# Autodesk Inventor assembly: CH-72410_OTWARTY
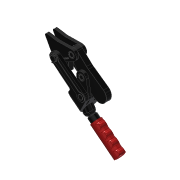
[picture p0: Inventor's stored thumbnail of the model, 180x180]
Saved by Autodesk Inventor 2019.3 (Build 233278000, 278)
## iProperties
Company: Î¢ÈíÖÐ¹ú
Created: 2012-10
Part Number: CH-72410_OTWARTY
Material: Ogólny
Description: STEP AP203
Document SubType Name: Assembly
Designer: CADENGINEERING4
Stock Number: DOCISKI CIĘŻIE
Sending System: SolidWorks 2010
Preprocessor: SwSTEP 2.0
Title: CH-72410.STEP
Author: Î¢ÈíÓÃ»§
Revision Number: ÈÎºÎ
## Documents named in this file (13)
- D:\Vault_2016\Projekty\NASZ KATALOG\CLAMPTEK\STRONA\Heavy duty weldables\CH-72410\CH-72410_OTWARTY.iam
- D:\Vault_2016\Projekty\NASZ KATALOG\CLAMPTEK\STRONA\Heavy duty weldables\CH-72410\72425-10.ipt
- D:\Vault_2016\Projekty\NASZ KATALOG\CLAMPTEK\STRONA\Heavy duty weldables\CH-72410\72425-06.ipt
- D:\Vault_2016\Projekty\NASZ KATALOG\CLAMPTEK\STRONA\Heavy duty weldables\CH-72410\M12.ipt
- D:\Vault_2016\Projekty\NASZ KATALOG\CLAMPTEK\STRONA\Heavy duty weldables\CH-72410\72425-07.ipt
- D:\Vault_2016\Projekty\NASZ KATALOG\CLAMPTEK\STRONA\Heavy duty weldables\CH-72410\CH-72410-03.ipt
- D:\Vault_2016\Projekty\NASZ KATALOG\CLAMPTEK\STRONA\Heavy duty weldables\CH-72410\72425-08.ipt
- D:\Vault_2016\Projekty\NASZ KATALOG\CLAMPTEK\STRONA\Heavy duty weldables\CH-72410\72425-11.ipt
- D:\Vault_2016\Projekty\NASZ KATALOG\CLAMPTEK\STRONA\Heavy duty weldables\CH-72410\CH-72410-01.ipt
- D:\Vault_2016\Projekty\NASZ KATALOG\CLAMPTEK\STRONA\Heavy duty weldables\CH-72410\CH-72410-02-02.ipt
- D:\Vault_2016\Projekty\NASZ KATALOG\CLAMPTEK\STRONA\Heavy duty weldables\CH-72410\CH-72410-02.ipt
- D:\Vault_2016\Projekty\NASZ KATALOG\CLAMPTEK\STRONA\Heavy duty weldables\CH-72410\72425-04.ipt
- D:\Vault_2016\Projekty\NASZ KATALOG\CLAMPTEK\STRONA\Heavy duty weldables\CH-72410\72425-03.ipt
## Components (23 placed, 12 different names)
1. CH-72410-01_12
2. CH-72410-02-02_14
3. CH-72410-02_17
4. 72425-10:2 — Zestawiające:2, Zestawiające:3, Zestawiające:4, Zestawiające:5, Zestawiające:20, Zestawiające:21, Zestawiające:42, Zestawiające:46
5. 72425-06:11 — Zestawiające:5, Zestawiające:19
6. M12:2 — Zestawiające:3, Zestawiające:22, Zestawiające:43
7. 72425-06:12 — Zestawiające:21, Równoległe:2
8. 72425-06:13 — Zestawiające:42, Zestawiające:43
9. 72425-07:2 — Zestawiające:9, Równoległe:1, Zestawiające:14, Zestawiające:17, Równoległe:3, Zestawiające:27, Zestawiające:33, Zestawiające:35, Zestawiające:36, Równoległe:8
10. 72425-06:14 — Zestawiające:6, Zestawiające:29, Zestawiające:31
11. CH-72410-03:2 — Zestawiające:7, Zestawiające:10, Zestawiające:11, Zestawiające:16, Zestawiające:25, Zestawiające:26, Zestawiające:28, Równoległe:4, Zestawiające:31, Zestawiające:32, Zestawiające:41
12. 72425-06:15 — Zestawiające:15, Zestawiające:39, Zestawiające:40, Równoległe:7
13. 72425-08:3 — Zestawiające:15, Zestawiające:16, Zestawiające:37, Zestawiające:38, Zestawiające:39, Zestawiające:41, Równoległe:6
14. 72425-11:2 — Zestawiające:1, Zestawiające:44
15. 72425-08:4 — Zestawiające:6, Zestawiające:7, Zestawiające:8, Zestawiające:28, Zestawiające:29, Zestawiające:30, Równoległe:4
16. 72425-06:16 — Zestawiające:37, Równoległe:5
17. 72425-06:17 — Zestawiające:2, Zestawiające:18
18. 72425-06:18 — Zestawiające:14, Zestawiające:35, Równoległe:9
19. 72425-06:19 — Zestawiające:8, Zestawiające:30, Zestawiające:32
20. 72425-06:20 — Zestawiające:33, Zestawiające:34, Równoległe:10
21. 72425-04:2 — Zestawiające:1, Zestawiające:4, Zestawiające:9, Równoległe:1, Zestawiające:12, Zestawiające:13, Zestawiające:18, Zestawiające:19, Zestawiające:20, Równoległe:2, Zestawiające:22, Zestawiające:23, Zestawiające:24, Równoległe:3, Zestawiające:27, Zestawiające:44, Zestawiające:46
22. 72425-03:3 — Zestawiające:11, Zestawiające:13, Zestawiające:24, Zestawiające:25, Zestawiające:34, Zestawiające:38, Równoległe:5, Równoległe:6, Równoległe:10
23. 72425-03:4 — Zestawiające:10, Zestawiające:12, Zestawiające:17, Zestawiające:23, Zestawiające:26, Zestawiające:36, Zestawiające:40, Równoległe:7, Równoległe:8, Równoległe:9
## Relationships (55: Mate 45, Flush 10)
- Zestawiające:1 [Mate]: 72425-11:2 ↔ 72425-04:2
- Zestawiające:2 [Mate]: 72425-10:2 ↔ 72425-06:17
- Zestawiające:3 [Mate]: 72425-10:2 ↔ M12:2
- Zestawiające:4 [Mate]: 72425-10:2 ↔ 72425-04:2
- Zestawiające:5 [Mate]: 72425-10:2 ↔ 72425-06:11
- Zestawiające:6 [Mate]: 72425-06:14 ↔ 72425-08:4
- Zestawiające:7 [Mate]: CH-72410-03:2 ↔ 72425-08:4
- Zestawiające:8 [Mate]: 72425-08:4 ↔ 72425-06:19
- Zestawiające:9 [Mate]: 72425-07:2 ↔ 72425-04:2
- Równoległe:1 [Flush]: 72425-07:2 ↔ 72425-04:2
- Zestawiające:10 [Mate]: CH-72410-03:2 ↔ 72425-03:4
- Zestawiające:11 [Mate]: CH-72410-03:2 ↔ 72425-03:3
- Zestawiające:12 [Mate]: 72425-04:2 ↔ 72425-03:4
- Zestawiające:13 [Mate]: 72425-04:2 ↔ 72425-03:3
- Zestawiające:14 [Mate]: 72425-07:2 ↔ 72425-06:18
- Zestawiające:15 [Mate]: 72425-06:15 ↔ 72425-08:3
- Zestawiające:16 [Mate]: CH-72410-03:2 ↔ 72425-08:3
- Zestawiające:17 [Mate]: 72425-07:2 ↔ 72425-03:4
- Zestawiające:18 [Mate]: 72425-06:17 ↔ 72425-04:2
- Zestawiające:19 [Mate]: 72425-06:11 ↔ 72425-04:2
- Zestawiające:20 [Mate]: 72425-10:2 ↔ 72425-04:2
- Zestawiające:21 [Mate]: 72425-10:2 ↔ 72425-06:12
- Równoległe:2 [Flush]: 72425-06:12 ↔ 72425-04:2
- Zestawiające:22 [Mate]: M12:2 ↔ 72425-04:2
- Zestawiające:23 [Mate]: 72425-04:2 ↔ 72425-03:4
- Zestawiające:24 [Mate]: 72425-04:2 ↔ 72425-03:3
- Zestawiające:25 [Mate]: CH-72410-03:2 ↔ 72425-03:3
- Zestawiające:26 [Mate]: CH-72410-03:2 ↔ 72425-03:4
- Równoległe:3 [Flush]: 72425-07:2 ↔ 72425-04:2
- Zestawiające:27 [Mate]: 72425-07:2 ↔ 72425-04:2
- Zestawiające:28 [Mate]: CH-72410-03:2 ↔ 72425-08:4
- Zestawiające:29 [Mate]: 72425-06:14 ↔ 72425-08:4
- Zestawiające:30 [Mate]: 72425-08:4 ↔ 72425-06:19
- Równoległe:4 [Flush]: CH-72410-03:2 ↔ 72425-08:4
- Zestawiające:31 [Mate]: 72425-06:14 ↔ CH-72410-03:2
- Zestawiające:32 [Mate]: CH-72410-03:2 ↔ 72425-06:19
- Zestawiające:33 [Mate]: 72425-07:2 ↔ 72425-06:20
- Zestawiające:34 [Mate]: 72425-06:20 ↔ 72425-03:3
- Zestawiające:35 [Mate]: 72425-07:2 ↔ 72425-06:18
- Zestawiające:36 [Mate]: 72425-07:2 ↔ 72425-03:4
- Zestawiające:37 [Mate]: 72425-08:3 ↔ 72425-06:16
- Zestawiające:38 [Mate]: 72425-08:3 ↔ 72425-03:3
- Zestawiające:39 [Mate]: 72425-06:15 ↔ 72425-08:3
- Zestawiające:40 [Mate]: 72425-06:15 ↔ 72425-03:4
- Zestawiające:41 [Mate]: CH-72410-03:2 ↔ 72425-08:3
- Równoległe:5 [Flush]: 72425-06:16 ↔ 72425-03:3
- Równoległe:6 [Flush]: 72425-08:3 ↔ 72425-03:3
- Równoległe:7 [Flush]: 72425-06:15 ↔ 72425-03:4
- Równoległe:8 [Flush]: 72425-07:2 ↔ 72425-03:4
- Zestawiające:42 [Mate]: 72425-10:2 ↔ 72425-06:13
- Zestawiające:43 [Mate]: M12:2 ↔ 72425-06:13
- Zestawiające:44 [Mate]: 72425-11:2 ↔ 72425-04:2
- Zestawiające:46 [Mate]: 72425-10:2 ↔ 72425-04:2
- Równoległe:9 [Flush]: 72425-06:18 ↔ 72425-03:4
- Równoległe:10 [Flush]: 72425-06:20 ↔ 72425-03:3
